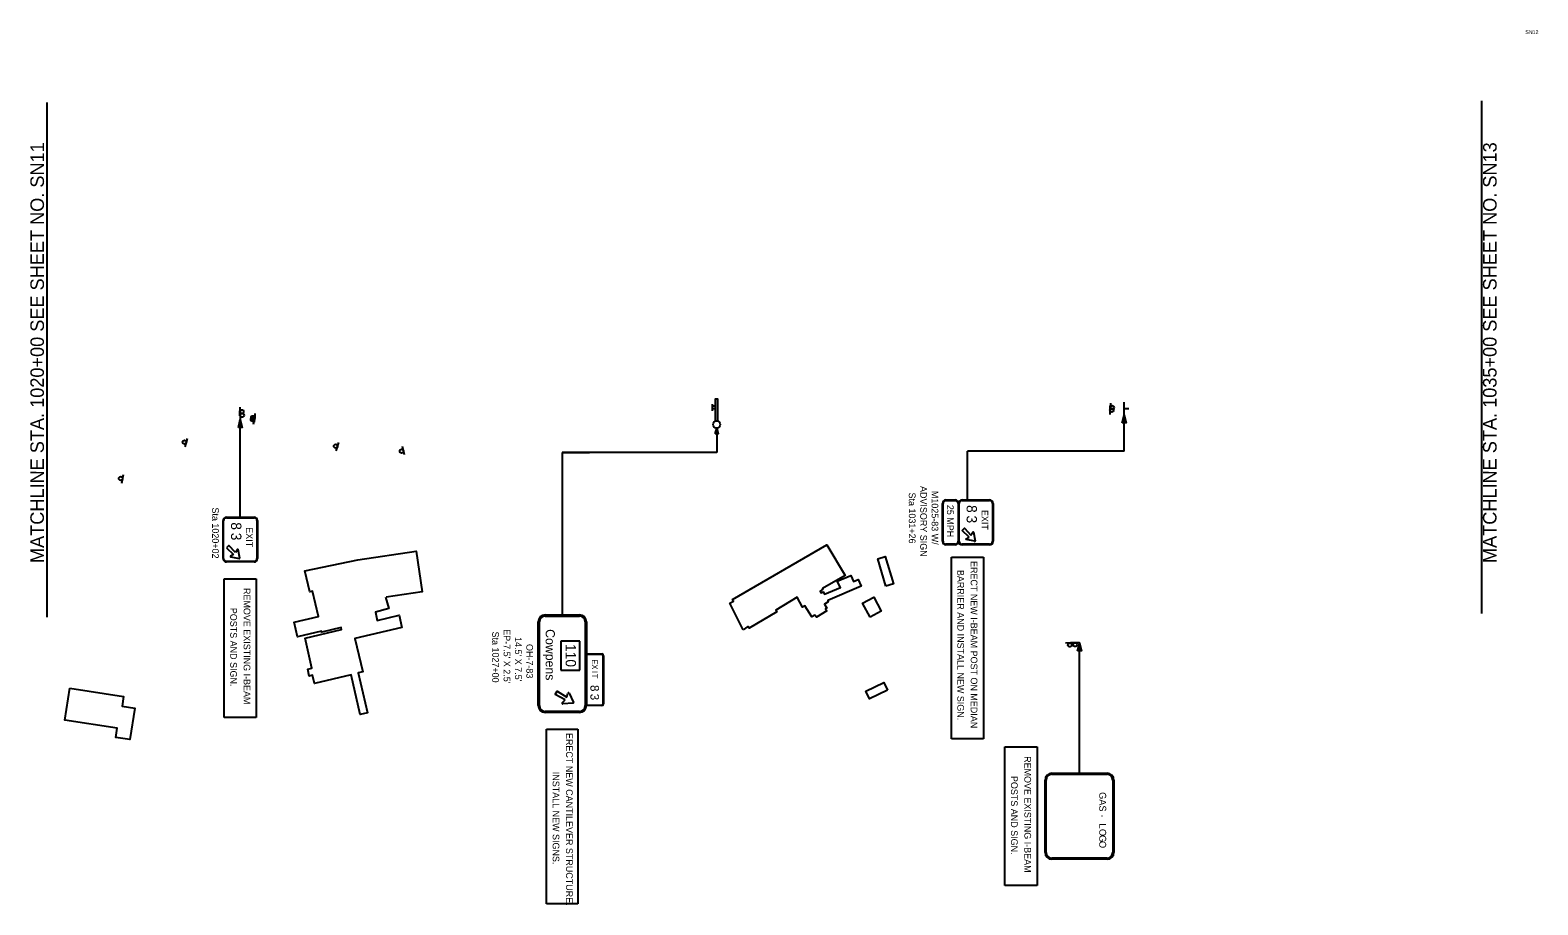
# Model space of a CAD drawing. Extents: x 1738756 to 1740332, y 1168920 to 1169834.
import ezdxf

# ---------------------------------------------------------------- set-up
doc = ezdxf.new("R2010")
doc.units = 0
for name, color, linetype in [('RD_EX_Bldg', 7, 'Continuous'), ('RD_SHT_MatchLine', 7, 'Continuous'), ('RD_SHT_TX', 7, 'Continuous'), ('SN_P_Signs', 7, 'Continuous')]:
    doc.layers.add(name, color=color, linetype=linetype)

msp = doc.modelspace()

# ---------------------------------------------------------------- linework, layer by layer
at = {"layer": 'RD_EX_Bldg'}
for points in [[(1739501.3, 1169207.5), (1739487.3, 1169235.2), (1739491.2, 1169237.4), (1739490.2, 1169239.2), (1739588.9, 1169296.5), (1739608, 1169264.3), (1739584.5, 1169250.7), (1739584.6, 1169250), (1739581.8, 1169247.9), (1739583.1, 1169246.3), (1739585.1, 1169247.1), (1739586.5, 1169244.8), (1739603, 1169251.6), (1739599.7, 1169258.3), (1739613.8, 1169264.3), (1739616.6, 1169257.9), (1739621.7, 1169260.1), (1739624.7, 1169253.3), (1739589.8, 1169238.1), (1739590.4, 1169236.6), (1739586.4, 1169234.4), (1739588.8, 1169230.3), (1739587.5, 1169229.3), (1739588.9, 1169227.5), (1739577.9, 1169220.7), (1739576.3, 1169222.9), (1739573.2, 1169221.2), (1739566, 1169232.6), (1739563.5, 1169231.3), (1739557.9, 1169241.6), (1739535.6, 1169228.1), (1739536.6, 1169226.4), (1739507.6, 1169209.4), (1739506.4, 1169211), (1739501.3, 1169207.5)], [(1739127.6, 1169241.7), (1739130.9, 1169229.7), (1739116.9, 1169225.8), (1739118.9, 1169217.4), (1739141.6, 1169222.7), (1739144.6, 1169209.8), (1739095.5, 1169198.3), (1739103.6, 1169163.6), (1739098.8, 1169162.5), (1739108.6, 1169120.7), (1739101.1, 1169118.9), (1739091.4, 1169160.4), (1739053.1, 1169151.4), (1739051.1, 1169160), (1739047.8, 1169159.2), (1739046.1, 1169166.5), (1739050.6, 1169167.6), (1739043.3, 1169198.7), (1739081.5, 1169207.7), (1739081, 1169209.8), (1739060.8, 1169205.1), (1739060.5, 1169206.1), (1739035.4, 1169200.2), (1739031.8, 1169215.5), (1739057.4, 1169221.5), (1739051.2, 1169247.9), (1739048.4, 1169247.3), (1739043.2, 1169269.1), (1739098.4, 1169280.8), (1739159.6, 1169289.6), (1739165.7, 1169247.2), (1739128.2, 1169241.8)], [(1739650.6, 1169253.3), (1739642.1, 1169281.6), (1739650, 1169284), (1739658.5, 1169255.7), (1739650.6, 1169253.3)], [(1739634, 1169220.8), (1739626.3, 1169235.5), (1739638, 1169241.6), (1739645.7, 1169226.9), (1739634, 1169220.8)], [(1738797.4, 1169146.5), (1738853.6, 1169137.7), (1738852.1, 1169127.7), (1738865.3, 1169125.7), (1738860.2, 1169092.8), (1738845.4, 1169095.1), (1738846.9, 1169104.7), (1738792.2, 1169113.2), (1738797.4, 1169146.5)], [(1739652.3, 1169144.3), (1739633.6, 1169135.4), (1739629.7, 1169143.5), (1739648.5, 1169152.4), (1739652.3, 1169144.3)]]:
    msp.add_lwpolyline(points, dxfattribs=at)
at = {"layer": 'RD_SHT_MatchLine'}
for points in [[(1738773.7, 1169220.7), (1738773.7, 1169494), (1738773.7, 1169758.5)], [(1740273.7, 1169224.5), (1740273.7, 1169494), (1740273.7, 1169760.4)]]:
    msp.add_lwpolyline(points, dxfattribs=at)
at = {"layer": 'SN_P_Signs'}
for p, q in [((1738975.3, 1169440.2), (1738974.9, 1169431.2)), ((1739472.1, 1169441.3), (1739469.3, 1169441.3)), ((1739472.1, 1169438.6), (1739469.3, 1169438.6)), ((1739469.4, 1169436.5), (1739469.4, 1169443.4)), ((1739885.4, 1169444.4), (1739884.8, 1169435.4)), ((1739884.9, 1169441.6), (1739884.8, 1169432.6)), ((1739899.7, 1169432.2), (1739899.7, 1169445.3)), ((1739899.7, 1169438.8), (1739904.7, 1169438.8)), ((1738975.5, 1169436.2), (1738975.6, 1169427.2)), ((1738975.6, 1169325.2), (1738975.6, 1169427.2)), ((1738989.6, 1169422.6), (1738991.3, 1169431.4)), ((1738990.5, 1169424.7), (1738991.3, 1169433.6)), ((1739899.7, 1169394.3), (1739899.7, 1169432.2)), ((1738918.1, 1169398.8), (1738920.3, 1169407.5)), ((1739473.7, 1169418.4), (1739473.7, 1169392.9)), ((1739076, 1169394.5), (1739078.6, 1169403.2)), ((1739147.3, 1169390.4), (1739145.3, 1169399.1)), ((1739312.3, 1169392.9), (1739312.3, 1169223.1)), ((1739473.7, 1169392.9), (1739312.3, 1169392.9)), ((1739312.3, 1169392.9), (1739340.7, 1169392.9)), ((1739735.9, 1169343.2), (1739735.9, 1169394.3)), ((1739899.7, 1169394.3), (1739735.9, 1169394.3)), ((1738851.7, 1169360.9), (1738853.5, 1169369.7)), ((1739713.4, 1169343.2), (1739723, 1169343.2)), ((1739713.4, 1169342.6), (1739723, 1169342.6)), ((1739730.2, 1169343.2), (1739759, 1169343.2)), ((1739730.2, 1169342.6), (1739759, 1169342.6)), ((1739709.8, 1169300), (1739709.8, 1169339.6)), ((1739710.4, 1169300), (1739710.4, 1169339.6)), ((1739726, 1169339.6), (1739726, 1169300)), ((1739726.6, 1169300), (1739726.6, 1169339.6)), ((1739726.6, 1169339.6), (1739726.6, 1169300)), ((1739727.2, 1169300), (1739727.2, 1169339.6)), ((1739762, 1169339.6), (1739762, 1169300)), ((1739762.6, 1169339.6), (1739762.6, 1169300)), ((1738957.6, 1169282), (1738957.6, 1169321.6)), ((1738958.2, 1169282), (1738958.2, 1169321.6)), ((1738961.2, 1169325.2), (1738990, 1169325.2)), ((1738961.2, 1169324.6), (1738990, 1169324.6)), ((1738993, 1169321.6), (1738993, 1169282)), ((1738993.6, 1169321.6), (1738993.6, 1169282)), ((1739723, 1169297), (1739713.4, 1169297)), ((1739723, 1169296.4), (1739713.4, 1169296.4)), ((1739759, 1169297), (1739730.2, 1169297)), ((1739759, 1169296.4), (1739730.2, 1169296.4)), ((1739719.1, 1169093.5), (1739719.1, 1169283.5)), ((1739719.1, 1169283.5), (1739752.7, 1169283.5)), ((1739752.7, 1169283.5), (1739752.7, 1169093.5)), ((1738990, 1169279), (1738961.2, 1169279)), ((1738990, 1169278.4), (1738961.2, 1169278.4)), ((1738958.8, 1169115.9), (1738958.8, 1169260.9)), ((1738958.8, 1169260.9), (1738992.4, 1169260.9)), ((1738992.4, 1169260.9), (1738992.4, 1169115.9)), ((1739330.6, 1169195.7), (1739310.9, 1169195.7)), ((1739310.9, 1169195.7), (1739310.9, 1169165.2)), ((1739330.6, 1169165.2), (1739330.6, 1169195.7)), ((1739847.4, 1169194), (1739838.4, 1169193.6)), ((1739853, 1169193.9), (1739844, 1169194.1)), ((1739853, 1169057.7), (1739853, 1169193.9)), ((1739310.9, 1169165.2), (1739330.6, 1169165.2)), ((1738992.4, 1169115.9), (1738958.8, 1169115.9)), ((1739295.9, 1168921.3), (1739295.9, 1169103.8)), ((1739295.9, 1169103.8), (1739328.7, 1169103.8)), ((1739328.7, 1169103.8), (1739328.7, 1168921.3)), ((1739752.7, 1169093.5), (1739719.1, 1169093.5)), ((1739775.1, 1168940.2), (1739775.1, 1169085.3)), ((1739775.1, 1169085.3), (1739808.8, 1169085.3)), ((1739808.8, 1169085.3), (1739808.8, 1168940.2)), ((1739808.8, 1168940.2), (1739775.1, 1168940.2)), ((1739328.7, 1168921.3), (1739295.9, 1168921.3))]:
    msp.add_line(p, q, dxfattribs=at)
for points in [[(1739474.9, 1169425.6), (1739474.9, 1169448.7), (1739472.1, 1169448.7), (1739472.1, 1169425.4)], [(1739730.2, 1169311.3), (1739732.7, 1169313.8), (1739739.5, 1169306.4)], [(1739737.6, 1169304.5), (1739730.2, 1169311.3)], [(1738970.5, 1169288.3), (1738963.8, 1169295.8), (1738961.2, 1169293.2)], [(1739734.5, 1169302.6), (1739737.6, 1169304.5)], [(1739743.5, 1169300), (1739734.6, 1169301.8)], [(1739739.5, 1169306.4), (1739741.4, 1169309.5)], [(1739742.2, 1169309.4), (1739744, 1169300.5)], [(1738961.2, 1169293.2), (1738968.6, 1169286.4)], [(1738968.6, 1169286.4), (1738965.5, 1169284.5)], [(1738965.6, 1169283.7), (1738974.5, 1169282)], [(1738972.4, 1169291.5), (1738970.5, 1169288.3)], [(1738975, 1169282.5), (1738973.3, 1169291.3)], [(1739294.3, 1169223.1), (1739330.3, 1169223.1)], [(1739294.3, 1169221.9), (1739330.3, 1169221.9)], [(1739287.1, 1169128.3), (1739287.1, 1169215.9)], [(1739288.3, 1169128.3), (1739288.3, 1169215.9)], [(1739336.3, 1169215.9), (1739336.3, 1169128.3)], [(1739337.5, 1169215.9), (1739337.5, 1169128.3)], [(1739353.7, 1169181.7), (1739337.5, 1169181.7), (1739337.5, 1169182.3), (1739353.7, 1169182.3)], [(1739354.9, 1169130.1), (1739354.9, 1169180.5)], [(1739355.5, 1169180.5), (1739355.5, 1169130.1)], [(1739304.8, 1169139.8), (1739306.9, 1169143.4), (1739316.9, 1169137.1)], [(1739315.3, 1169134.3), (1739304.8, 1169139.8)], [(1739316.9, 1169137.1), (1739318.2, 1169141.4)], [(1739319.3, 1169141.4), (1739324.1, 1169131.7)], [(1739330.3, 1169122.3), (1739294.3, 1169122.3)], [(1739312.3, 1169131.1), (1739315.3, 1169134.3)], [(1739323.6, 1169130.8), (1739312.8, 1169130.1)], [(1739353.7, 1169128.3), (1739337.5, 1169128.3), (1739337.5, 1169128.9)], [(1739337.5, 1169128.9), (1739353.7, 1169128.9)], [(1739330.3, 1169121.1), (1739294.3, 1169121.1)], [(1739817, 1168974.9), (1739817, 1169050.5)], [(1739818.2, 1168974.9), (1739818.2, 1169050.5)], [(1739824.2, 1169057.7), (1739881.8, 1169057.7)], [(1739824.2, 1169056.5), (1739881.8, 1169056.5)], [(1739887.8, 1169050.5), (1739887.8, 1168974.9)], [(1739889, 1169050.5), (1739889, 1168974.9)], [(1739881.8, 1168968.9), (1739824.2, 1168968.9)], [(1739881.8, 1168967.7), (1739824.2, 1168967.7)]]:
    msp.add_lwpolyline(points, dxfattribs=at)
for points in [[(1738973.6, 1169419), (1738975.6, 1169427.2), (1738977.7, 1169419)], [(1739897.7, 1169424), (1739899.7, 1169432.2), (1739901.8, 1169424)], [(1739472.2, 1169412.2), (1739473.7, 1169418.4), (1739475.3, 1169412.2)], [(1739851, 1169185.7), (1739853, 1169193.9), (1739855.1, 1169185.7)]]:
    msp.add_lwpolyline(points, close=True, dxfattribs=at)
for centre, radius in [((1738977.1, 1169435.6), 2), ((1739886.9, 1169437.1), 2), ((1739887.1, 1169439.8), 2), ((1738977.6, 1169431.7), 2), ((1738988.5, 1169427.4), 2), ((1738988.9, 1169429.3), 2), ((1739473.7, 1169422.1), 3.71), ((1738917.3, 1169403.6), 2), ((1739075.4, 1169399.5), 2), ((1739144.3, 1169394.3), 2), ((1738850.6, 1169365.7), 2), ((1739843, 1169191.7), 2), ((1739848.5, 1169192), 2)]:
    msp.add_circle(centre, radius, dxfattribs=at)
for centre, radius, start, end in [((1739713.4, 1169339.6), 3.6, 90, 180), ((1739713.4, 1169339.6), 3, 90, 180), ((1739723, 1169339.6), 3.6, 360, 90), ((1739723, 1169339.6), 3, 360, 90), ((1739730.2, 1169339.6), 3.6, 90, 180), ((1739730.2, 1169339.6), 3, 90, 180), ((1739759, 1169339.6), 3.6, 360, 90), ((1739759, 1169339.6), 3, 360, 90), ((1738961.2, 1169321.6), 3.6, 90, 180), ((1738961.2, 1169321.6), 3, 90, 180), ((1738990, 1169321.6), 3.6, 360, 90), ((1738990, 1169321.6), 3, 360, 90), ((1739713.4, 1169300), 3.6, 180, 270), ((1739713.4, 1169300), 3, 180, 270), ((1739723, 1169300), 3.6, 270, 360), ((1739723, 1169300), 3, 270, 360), ((1739730.2, 1169300), 3.6, 180, 270), ((1739730.2, 1169300), 3, 180, 270), ((1739734.7, 1169302.2), 0.45, 121.0379, 258.8221), ((1739741.8, 1169309.3), 0.45, 11.1779, 148.9621), ((1739743.5, 1169300.4), 0.45, 258.8221, 11.1779), ((1739759, 1169300), 3, 270, 360), ((1739759, 1169300), 3.6, 270, 360), ((1738961.2, 1169282), 3.6, 180, 270), ((1738961.2, 1169282), 3, 180, 270), ((1738965.7, 1169284.2), 0.45, 121.0379, 258.8221), ((1738972.8, 1169291.3), 0.45, 11.1779, 148.9621), ((1738974.6, 1169282.4), 0.45, 258.8221, 11.1779), ((1738990, 1169282), 3, 270, 360), ((1738990, 1169282), 3.6, 270, 360), ((1739294.3, 1169215.9), 7.2, 90, 180), ((1739294.3, 1169215.9), 6, 90, 180), ((1739330.3, 1169215.9), 7.2, 0, 90), ((1739330.3, 1169215.9), 6, 0, 90), ((1739353.7, 1169180.5), 1.8, 0, 90), ((1739353.7, 1169180.5), 1.2, 0, 90), ((1739318.8, 1169141.2), 0.6, 25.9807, 163.4461), ((1739294.3, 1169128.3), 7.2, 180, 270), ((1739294.3, 1169128.3), 6, 180, 270), ((1739312.7, 1169130.7), 0.6, 136.5539, 274.0194), ((1739323.5, 1169131.4), 0.6, 274.0194, 25.9807), ((1739330.3, 1169128.3), 6, 270, 0), ((1739330.3, 1169128.3), 7.2, 270, 0), ((1739353.7, 1169130.1), 1.8, 270, 0), ((1739353.7, 1169130.1), 1.2, 270, 0), ((1739824.2, 1169050.5), 7.2, 90, 180), ((1739824.2, 1169050.5), 6, 90, 180), ((1739881.8, 1169050.5), 7.2, 0, 90), ((1739881.8, 1169050.5), 6, 0, 90), ((1739824.2, 1168974.9), 7.2, 180, 270), ((1739824.2, 1168974.9), 6, 180, 270), ((1739881.8, 1168974.9), 6, 270, 0), ((1739881.8, 1168974.9), 7.2, 270, 0)]:
    msp.add_arc(centre, radius, start, end, dxfattribs=at)

# ---------------------------------------------------------------- texts
at = {"layer": 'RD_SHT_TX'}
msp.add_text('SN12', height=4, dxfattribs=at).set_placement((1740319.1, 1169830.2))
for s, p in [('MATCHLINE STA. 1020+00 SEE SHEET NO. SN11', (1738770.3, 1169277.3)), ('MATCHLINE STA. 1035+00 SEE SHEET NO. SN13', (1740289, 1169277.3))]:
    msp.add_text(s, height=14.173, rotation=89.9856, dxfattribs=at).set_placement(p)
at = {"layer": 'SN_P_Signs'}
for s, height, rotation, p in [('Sta 1031+26', 7, 270.0001, (1739674.6, 1169351)), ('ADVISORY SIGN', 7, 270.0001, (1739686.5, 1169357.8)), ('M1025-83 W/', 7, 270.0001, (1739698.4, 1169352.7)), ('Sta 1020+02', 7, 270.0001, (1738946.2, 1169335.4)), ('25 MPH', 7, 270, (1739714.5, 1169338.1)), ('8', 10.8, 270, (1739735, 1169337.9)), ('3', 10.8, 270, (1739735, 1169327)), ('EXIT', 7, 270, (1739750.6, 1169332.8)), ('8', 10.8, 270, (1738966, 1169319.9)), ('EXIT', 7, 270, (1738981.6, 1169314.7)), ('3', 10.8, 270, (1738966, 1169309)), ('BARRIER AND INSTALL NEW SIGN.', 7, 270.0001, (1739725.3, 1169270.1)), ('ERECT NEW I-BEAM POST ON MEDIAN', 7, 270.0001, (1739739.3, 1169279.4)), ('REMOVE EXISTING I-BEAM', 7, 270.0001, (1738979.1, 1169251.2)), ('POSTS AND SIGN.', 7, 270.0001, (1738965.1, 1169230.5)), ('Sta 1027+00', 7, 270.0001, (1739239, 1169205.7)), ("EP-7.5' X 2.5'", 7, 270.0001, (1739250.9, 1169208.1)), ('Cowpens', 9.6, 270, (1739294.9, 1169208.2)), ("14.5' X 7.5'", 7, 270.0001, (1739262.8, 1169199.9)), ('OH-7-83', 7, 270.0001, (1739274.7, 1169192.7)), ('110', 10.8, 270, (1739315.8, 1169192.7)), ('E', 6, 270, (1739343.2, 1169176.6)), ('X', 6, 270, (1739343.2, 1169171.4)), ('I', 6, 270, (1739343.2, 1169164.6)), ('T', 6, 270, (1739343.2, 1169161.6)), ('8', 9, 270, (1739341.7, 1169149.8)), ('3', 9, 270, (1739341.7, 1169140.7)), ('ERECT NEW CANTILEVER STRUCTURE.', 7, 270.0001, (1739316.2, 1169099.7)), ('REMOVE EXISTING I-BEAM', 7, 270.0001, (1739795.4, 1169075.5)), ('INSTALL NEW SIGNS.', 7, 270.0001, (1739302.2, 1169059.1)), ('POSTS AND SIGN.', 7, 270.0001, (1739781.4, 1169054.8)), ('GAS', 7.2, 270, (1739873.7, 1169037.9)), ('-', 7.2, 270, (1739873.7, 1169014.5)), ('-', 7.2, 270, (1739873.7, 1169014.5)), ('O', 7.2, 270, (1739873.7, 1168999.4)), ('O', 7.2, 270, (1739873.7, 1168999.4)), ('L', 7.2, 270, (1739873.7, 1169005.2)), ('L', 7.2, 270, (1739873.7, 1169005.2)), ('G', 7.2, 270, (1739873.7, 1168993)), ('G', 7.2, 270, (1739873.7, 1168993)), ('O', 7.2, 270, (1739873.7, 1168986.8)), ('O', 7.2, 270, (1739873.7, 1168986.8))]:
    msp.add_text(s, height=height, rotation=rotation, dxfattribs=at).set_placement(p)

doc.saveas('drawing.dxf')
